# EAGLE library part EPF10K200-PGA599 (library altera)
EPF10K200 FLEX 10K family
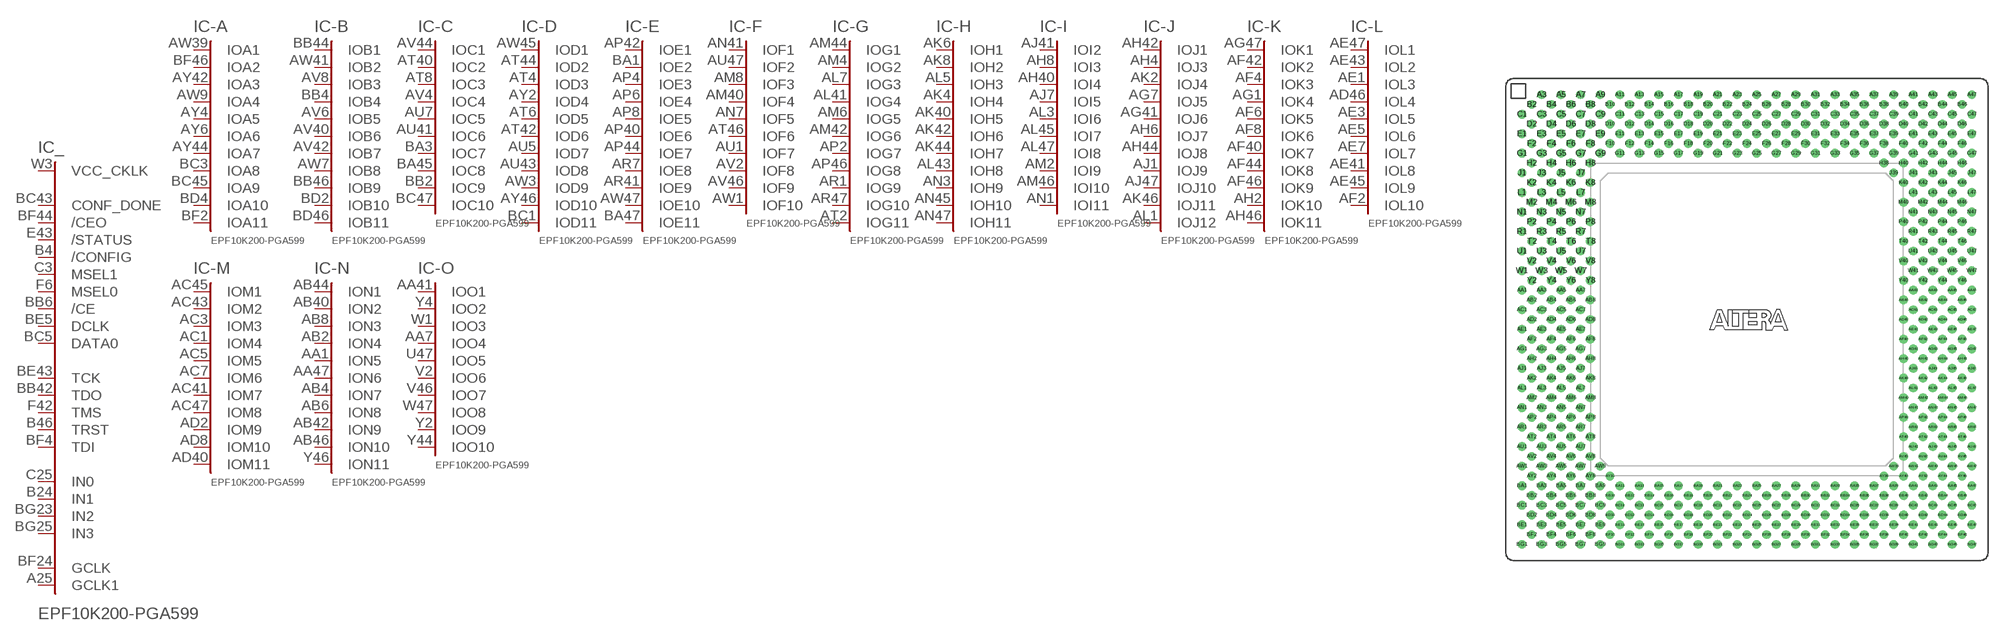
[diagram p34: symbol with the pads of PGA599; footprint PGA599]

Designator prefix IC; gates _=200P599C -A=A11-599 -B=B11-599 -C=C10-599 -D=D11-599 -E=E11-599 -F=F10-599 -G=G11-599 -H=H11-599 -I=I11-599 -J=J12-599 -K=K11-599 -L=L10-599 -M=M11-599 -N=N11-599 -O=O10-599 -P=P11-599 -Q=Q11-599 -R=R10-599 -S=S11-599 -T=T11-599 -U=U10-599 -V=V11-599 -W=W11-599 -X=X10-599 -1=IO44 -2=IO84 -3=IO124 -4=IO164 -5=IO204 -6=IO244 -7=IO284 -8=IO324 -9=IO364 -10=IO404 -11=IO444 -12=IO484 -13=IO524 G1=GND G2=GND G3=GND G4=GND G5=GND G6=GND G7=GND G8=GND G9=GND G10=GND G11=GND G12=GND G13=GND G14=GND G15=GND G16=GND G17=GND G18=GND G19=GND G20=GND G21=GND G22=GND G23=GND G24=GND G25=GND G26=GND G27=GND G28=GND G29=GND G30=GND G31=GND G32=GND G33=GND G34=GND G35=GND G36=GND G37=GND G38=GND G39=GND G40=GND G41=GND G42=GND G43=GND G44=GND G45=GND G46=GND G47=GND G48=GND G49=GND G50=GND G51=GND G52=GND G53=GND G54=GND G55=GND G56=GND G57=GND V1=VCCINT V2=VCCINT V3=VCCINT V4=VCCINT V5=VCCINT V6=VCCINT V7=VCCINT V8=VCCINT V9=VCCINT V10=VCCINT V11=VCCINT V12=VCCINT V13=VCCINT V14=VCCINT V15=VCCINT V16=VCCINT V17=VCCINT V18=VCCINT V19=VCCINT V20=VCCINT V21=VCCINT V22=VCCINT V23=VCCINT V24=VCCINT V25=VCCINT VO1=VCCIO VO2=VCCIO VO3=VCCIO VO4=VCCIO VO5=VCCIO VO6=VCCIO VO7=VCCIO VO8=VCCIO VO9=VCCIO VO10=VCCIO VO11=VCCIO VO12=VCCIO VO13=VCCIO VO14=VCCIO VO15=VCCIO VO16=VCCIO VO17=VCCIO VO18=VCCIO VO19=VCCIO VO20=VCCIO VO21=VCCIO VO22=VCCIO VO23=VCCIO VO24=VCCIO VO25=VCCIO VO26=VCCIO VO27=VCCIO VO28=VCCIO VO29=VCCIO VO30=VCCIO VO31=VCCIO VO32=VCCIO

## EPF10K200-PGA599 (OC_FARNELL: unknown; OC_NEWARK: unknown)  [PGA599]
A3  V5:VCC  pwr
A5  -2:IO52
A7  -2:IO82
A9  -3:IO101
A11  -3:IO111
A13  -4:IO131
A15  -4:IO161
A17  -5:IO191
A19  -6:IO214
A21  -6:IO234
A23  -7:IO263
A25  _:GCLK1  in
A27  -7:IO282
A29  -8:IO301
A31  -8:IO321
A33  -9:IO353
A35  -10:IO381
A37  -10:IO402
A39  -11:IO411
A41  -11:IO431
A43  -12:IO471
A45  V6:VCC  pwr
A47  G15:GND  pwr
AA1  -N:ION5
AA3  G1:GND  pwr
AA5  VO1:VCCIO  pwr
AA7  -O:IOO4
AA41  -O:IOO1
AA43  VO2:VCCIO  pwr
AA45  G2:GND  pwr
AA47  -N:ION6
AB2  -N:ION4
AB4  -N:ION7
AB6  -N:ION8
AB8  -N:ION3
AB40  -N:ION2
AB42  -N:ION9
AB44  -N:ION1
AB46  -N:ION10
AC1  -M:IOM4
AC3  -M:IOM3
AC5  -M:IOM5
AC7  -M:IOM6
AC41  -M:IOM7
AC43  -M:IOM2
AC45  -M:IOM1
AC47  -M:IOM8
AD2  -M:IOM9
AD4  VO3:VCCIO  pwr
AD6  G3:GND  pwr
AD8  -M:IOM10
AD40  -M:IOM11
AD42  G4:GND  pwr
AD44  VO4:VCCIO  pwr
AD46  -L:IOL4
AE1  -L:IOL3
AE3  -L:IOL5
AE5  -L:IOL6
AE7  -L:IOL7
AE41  -L:IOL8
AE43  -L:IOL2
AE45  -L:IOL9
AE47  -L:IOL1
AF2  -L:IOL10
AF4  -K:IOK3
AF6  -K:IOK5
AF8  -K:IOK6
AF40  -K:IOK7
AF42  -K:IOK2
AF44  -K:IOK8
AF46  -K:IOK9
AG1  -K:IOK4
AG3  G5:GND  pwr
AG5  VO5:VCCIO  pwr
AG7  -J:IOJ5
AG41  -J:IOJ6
AG43  VO6:VCCIO  pwr
AG45  G6:GND  pwr
AG47  -K:IOK1
AH2  -K:IOK10
AH4  -J:IOJ3
AH6  -J:IOJ7
AH8  -I:IOI3
AH40  -I:IOI4
AH42  -J:IOJ1
AH44  -J:IOJ8
AH46  -K:IOK11
AJ1  -J:IOJ9
AJ3  V1:VCC  pwr
AJ5  G7:GND  pwr
AJ7  -I:IOI5
AJ41  -I:IOI2
AJ43  G8:GND  pwr
AJ45  V2:VCC  pwr
AJ47  -J:IOJ10
AK2  -J:IOJ4
AK4  -H:IOH4
AK6  -H:IOH1
AK8  -H:IOH2
AK40  -H:IOH5
AK42  -H:IOH6
AK44  -H:IOH7
AK46  -J:IOJ11
AL1  -J:IOJ12
AL3  -I:IOI6
AL5  -H:IOH3
AL7  -G:IOG3
AL41  -G:IOG4
AL43  -H:IOH8
AL45  -I:IOI7
AL47  -I:IOI8
AM2  -I:IOI9
AM4  -G:IOG2
AM6  -G:IOG5
AM8  -F:IOF3
AM40  -F:IOF4
AM42  -G:IOG6
AM44  -G:IOG1
AM46  -I:IOI10
AN1  -I:IOI11
AN3  -H:IOH9
AN5  VO7:VCCIO  pwr
AN7  -F:IOF5
AN41  -F:IOF1
AN43  VO8:VCCIO  pwr
AN45  -H:IOH10
AN47  -H:IOH11
AP2  -G:IOG7
AP4  -E:IOE3
AP6  -E:IOE4
AP8  -E:IOE5
AP40  -E:IOE6
AP42  -E:IOE1
AP44  -E:IOE7
AP46  -G:IOG8
AR1  -G:IOG9
AR3  G9:GND  pwr
AR5  G10:GND  pwr
AR7  -E:IOE8
AR41  -E:IOE9
AR43  G11:GND  pwr
AR45  G12:GND  pwr
AR47  -G:IOG10
AT2  -G:IOG11
AT4  -D:IOD3
AT6  -D:IOD5
AT8  -C:IOC3
AT40  -C:IOC2
AT42  -D:IOD6
AT44  -D:IOD2
AT46  -F:IOF6
AU1  -F:IOF7
AU3  V3:VCC  pwr
AU5  -D:IOD7
AU7  -C:IOC5
AU41  -C:IOC6
AU43  -D:IOD8
AU45  V4:VCC  pwr
AU47  -F:IOF2
AV2  -F:IOF8
AV4  -C:IOC4
AV6  -B:IOB5
AV8  -B:IOB3
AV40  -B:IOB6
AV42  -B:IOB7
AV44  -C:IOC1
AV46  -F:IOF9
AW1  -F:IOF10
AW3  -D:IOD9
AW5  VO9:VCCIO  pwr
AW7  -B:IOB8
AW9  -A:IOA4
AW39  -A:IOA1
AW41  -B:IOB2
AW43  VO10:VCCIO  pwr
AW45  -D:IOD1
AW47  -E:IOE10
AY2  -D:IOD4
AY4  -A:IOA5
AY6  -A:IOA6
AY8  G13:GND  pwr
AY10  -1:IO12
AY38  -13:IO522
AY40  G14:GND  pwr
AY42  -A:IOA3
AY44  -A:IOA7
AY46  -D:IOD10
B2  G34:GND  pwr
B4  _:/CONFIG  in
B6  -1:IO21
B8  -2:IO74
B10  -3:IO91
B12  -3:IO121
B14  -4:IO141
B16  -5:IO171
B18  -5:IO201
B20  -6:IO224
B22  -6:IO244
B24  _:IN1  in
B26  -7:IO274
B28  -8:IO291
B30  -8:IO311
B32  -9:IO344
B34  -10:IO373
B36  -10:IO391
B38  -11:IO424
B40  -11:IO444
B42  -12:IO481
B44  -13:IO514
B46  _:TRST
BA1  -E:IOE2
BA3  -C:IOC7
BA5  G16:GND  pwr
BA7  VO11:VCCIO  pwr
BA9  -1:IO22
BA11  -1:IO42
BA13  -2:IO72
BA15  -3:IO103
BA17  -4:IO142
BA19  -5:IO183
BA21  -6:IO223
BA23  -7:IO252
BA25  -7:IO283
BA27  -8:IO313
BA29  -9:IO352
BA31  -10:IO392
BA33  -11:IO432
BA35  -12:IO463
BA37  -13:IO492
BA39  -13:IO512
BA41  VO12:VCCIO  pwr
BA43  G17:GND  pwr
BA45  -C:IOC8
BA47  -E:IOE11
BB2  -C:IOC9
BB4  -B:IOB4
BB6  _:/CE  in
BB8  -1:IO32
BB10  -2:IO53
BB12  -2:IO83
BB14  -3:IO113
BB16  -4:IO132
BB18  -5:IO173
BB20  -6:IO213
BB22  -6:IO243
BB24  G18:GND  pwr
BB26  -8:IO292
BB28  -8:IO323
BB30  -9:IO363
BB32  -10:IO403
BB34  -11:IO422
BB36  -12:IO452
BB38  -12:IO483
BB40  -13:IO502
BB42  _:TDO
BB44  -B:IOB1
BB46  -B:IOB9
BC1  -D:IOD11
BC3  -A:IOA8
BC5  _:DATA0  in
BC7  G19:GND  pwr
BC9  VO13:VCCIO  pwr
BC11  -2:IO62
BC13  G20:GND  pwr
BC15  VO14:VCCIO  pwr
BC17  -5:IO193
BC19  G21:GND  pwr
BC21  VO15:VCCIO  pwr
BC23  -7:IO261
BC25  -7:IO272
BC27  VO16:VCCIO  pwr
BC29  G22:GND  pwr
BC31  -9:IO342
BC33  VO17:VCCIO  pwr
BC35  G23:GND  pwr
BC37  -12:IO473
BC39  VO18:VCCIO  pwr
BC41  G24:GND  pwr
BC43  _:CONF_DONE  in
BC45  -A:IOA9
BC47  -C:IOC10
BD2  -B:IOB10
BD4  -A:IOA10
BD6  -1:IO13
BD8  -1:IO33
BD10  -3:IO93
BD12  -3:IO122
BD14  -4:IO152
BD16  -4:IO162
BD18  -5:IO203
BD20  -6:IO233
BD22  -7:IO251
BD24  VO19:VCCIO  pwr
BD26  -7:IO284
BD28  -8:IO303
BD30  -9:IO332
BD32  -10:IO372
BD34  -10:IO383
BD36  -11:IO412
BD38  -11:IO442
BD40  -13:IO501
BD42  -13:IO523
BD44  G25:GND  pwr
BD46  -B:IOB11
BE1  V7:VCC  pwr
BE3  G26:GND  pwr
BE5  _:DCLK  in
BE7  -1:IO43
BE9  -2:IO63
BE11  V8:VCC  pwr
BE13  G27:GND  pwr
BE15  -4:IO153
BE17  -5:IO182
BE19  V9:VCC  pwr
BE21  G28:GND  pwr
BE23  -7:IO262
BE25  -7:IO273
BE27  G29:GND  pwr
BE29  V10:VCC  pwr
BE31  -9:IO354
BE33  -10:IO382
BE35  G30:GND  pwr
BE37  V11:VCC  pwr
BE39  -12:IO472
BE41  -13:IO493
BE43  _:TCK
BE45  G31:GND  pwr
BE47  V12:VCC  pwr
BF2  -A:IOA11
BF4  _:TDI
BF6  -1:IO23
BF8  -2:IO73
BF10  -3:IO92
BF12  -3:IO123
BF14  -4:IO143
BF16  -5:IO172
BF18  -5:IO202
BF20  -6:IO222
BF22  -6:IO242
BF24  _:GCLK  in
BF26  -8:IO293
BF28  -8:IO312
BF30  -9:IO333
BF32  -9:IO364
BF34  -10:IO393
BF36  -11:IO413
BF38  -11:IO443
BF40  -12:IO462
BF42  -13:IO513
BF44  _:/CEO  in
BF46  -A:IOA2
BG1  G32:GND  pwr
BG3  V13:VCC  pwr
BG5  -2:IO54
BG7  -2:IO84
BG9  -3:IO102
BG11  -3:IO112
BG13  -4:IO133
BG15  -4:IO163
BG17  -5:IO192
BG19  -6:IO212
BG21  -6:IO232
BG23  _:IN2  in
BG25  _:IN3  in
BG27  -8:IO302
BG29  -8:IO322
BG31  -9:IO343
BG33  -10:IO371
BG35  -10:IO401
BG37  -11:IO423
BG39  -11:IO433
BG41  -12:IO453
BG43  -12:IO482
BG45  V14:VCC  pwr
BG47  G33:GND  pwr
C1  V15:VCC  pwr
C3  _:MSEL1  in
C5  -1:IO11
C7  -1:IO41
C9  -2:IO64
C11  V16:VCC  pwr
C13  G35:GND  pwr
C15  -4:IO151
C17  -5:IO181
C19  V17:VCC  pwr
C21  G36:GND  pwr
C23  -7:IO253
C25  _:IN0  in
C27  G37:GND  pwr
C29  V18:VCC  pwr
C31  -9:IO334
C33  -9:IO361
C35  G38:GND  pwr
C37  V19:VCC  pwr
C39  -12:IO461
C41  -13:IO503
C43  -13:IO524
C45  G39:GND  pwr
C47  V20:VCC  pwr
D2  -X:IOX5
D4  G40:GND  pwr
D6  -1:IO34
D8  -1:IO31
D10  -3:IO94
D12  -3:IO124
D14  -4:IO154
D16  -4:IO164
D18  -5:IO204
D20  -6:IO231
D22  -6:IO241
D24  VO20:VCCIO  pwr
D26  -8:IO294
D28  -8:IO304
D30  -9:IO331
D32  -10:IO374
D34  -10:IO384
D36  -11:IO414
D38  -11:IO441
D40  -12:IO474
D42  -13:IO491
D44  -X:IOX6
D46  -X:IOX7
E1  -X:IOX8
E3  -X:IOX4
E5  V21:VCC  pwr
E7  G41:GND  pwr
E9  VO21:VCCIO  pwr
E11  -2:IO61
E13  G42:GND  pwr
E15  VO22:VCCIO  pwr
E17  -5:IO194
E19  G43:GND  pwr
E21  VO23:VCCIO  pwr
E23  -7:IO264
E25  -7:IO271
E27  VO24:VCCIO  pwr
E29  G44:GND  pwr
E31  -9:IO341
E33  VO25:VCCIO  pwr
E35  G45:GND  pwr
E37  -12:IO454
E39  VO26:VCCIO  pwr
E41  G46:GND  pwr
E43  _:/STATUS  in
E45  -X:IOX1
E47  -W:IOW4
F2  -W:IOW5
F4  -W:IOW2
F6  _:MSEL0  in
F8  -1:IO24
F10  -2:IO51
F12  -2:IO81
F14  -3:IO114
F16  -4:IO134
F18  -5:IO174
F20  -6:IO211
F22  -7:IO254
F24  G47:GND  pwr
F26  -7:IO281
F28  -8:IO324
F30  -9:IO362
F32  -10:IO404
F34  -11:IO421
F36  -12:IO464
F38  -12:IO484
F40  -13:IO504
F42  _:TMS
F44  -W:IOW6
F46  -W:IOW1
G1  -U:IOU5
G3  -V:IOV5
G5  G48:GND  pwr
G7  VO27:VCCIO  pwr
G9  -1:IO14
G11  -1:IO44
G13  -2:IO71
G15  -3:IO104
G17  -4:IO144
G19  -5:IO184
G21  -6:IO221
G23  G49:GND  pwr
G25  V22:VCC  pwr
G27  -8:IO314
G29  -9:IO351
G31  -10:IO394
G33  -11:IO434
G35  -12:IO451
G37  -13:IO494
G39  -13:IO511
G41  VO28:VCCIO  pwr
G43  G50:GND  pwr
G45  -V:IOV2
G47  -U:IOU1
H2  -U:IOU3
H4  -V:IOV3
H6  -X:IOX9
H8  -X:IOX3
H38  -13:IO521
H40  G51:GND  pwr
H42  -X:IOX2
H44  -V:IOV6
H46  -U:IOU6
J1  -T:IOT4
J3  -U:IOU7
J5  VO29:VCCIO  pwr
J7  -W:IOW7
J39  -X:IOX10
J41  -W:IOW8
J43  VO30:VCCIO  pwr
J45  -T:IOT5
J47  -T:IOT6
K2  -S:IOS4
K4  -V:IOV7
K6  -W:IOW9
K8  -W:IOW3
K40  -U:IOU9
K42  -W:IOW11
K44  -V:IOV8
K46  -S:IOS1
L1  -S:IOS5
L3  V23:VCC  pwr
L5  -V:IOV9
L7  -V:IOV4
L41  -V:IOV1
L43  -V:IOV10
L45  V24:VCC  pwr
L47  -S:IOS6
M2  -S:IOS7
M4  -U:IOU4
M6  -U:IOU8
M8  -V:IOV11
M40  -W:IOW10
M42  -U:IOU2
M44  -U:IOU10
M46  -R:IOR3
N1  -R:IOR4
N3  G52:GND  pwr
N5  G53:GND  pwr
N7  -T:IOT7
N41  -T:IOT8
N43  G54:GND  pwr
N45  G55:GND  pwr
N47  -R:IOR1
P2  -R:IOR5
P4  -T:IOT9
P6  -T:IOT2
P8  -T:IOT3
P40  -T:IOT10
P42  -T:IOT1
P44  -T:IOT11
P46  -R:IOR6
R1  -Q:IOQ2
R3  -R:IOR7
R5  VO31:VCCIO  pwr
R7  -S:IOS8
R41  -S:IOS2
R43  VO32:VCCIO  pwr
R45  -Q:IOQ4
R47  -Q:IOQ5
T2  -P:IOP4
T4  -R:IOR8
T6  -S:IOS9
T8  -S:IOS3
T40  -S:IOS10
T42  -S:IOS11
T44  -R:IOR2
T46  -P:IOP5
U1  -P:IOP6
U3  -P:IOP2
U5  -Q:IOQ6
U7  -R:IOR9
U41  -R:IOR10
U43  -Q:IOQ7
U45  -P:IOP1
U47  -O:IOO5
V2  -O:IOO6
V4  -Q:IOQ8
V6  -Q:IOQ3
V8  -Q:IOQ9
V40  -Q:IOQ10
V42  -Q:IOQ1
V44  -Q:IOQ11
V46  -O:IOO7
W1  -O:IOO3
W3  _:VCC_CKLK  pas
W5  G56:GND  pwr
W7  -P:IOP7
W41  -P:IOP8
W43  G57:GND  pwr
W45  V25:VCC  pwr
W47  -O:IOO8
Y2  -O:IOO9
Y4  -O:IOO2
Y6  -P:IOP3
Y8  -P:IOP9
Y40  -P:IOP10
Y42  -P:IOP11
Y44  -O:IOO10
Y46  -N:ION11

## Footprint PGA599 (pad centres in mm)
Pin Grid Array
drill 0.61 pad 1.016 round: A3 -26.67,29.21; A5 -24.13,29.21; A7 -21.59,29.21; A9 -19.05,29.21; A11 -16.51,29.21; A13 -13.97,29.21; A15 -11.43,29.21; A17 -8.89,29.21; A19 -6.35,29.21; A21 -3.81,29.21; A23 -1.27,29.21; A25 1.27,29.21; A27 3.81,29.21; A29 6.35,29.21; A31 8.89,29.21; A33 11.43,29.21; A35 13.97,29.21; A37 16.51,29.21; A39 19.05,29.21; A41 21.59,29.21; A43 24.13,29.21; A45 26.67,29.21; A47 29.21,29.21; AA1 -29.21,3.81; AA3 -26.67,3.81; AA5 -24.13,3.81; AA7 -21.59,3.81; AA41 21.59,3.81; AA43 24.13,3.81; AA45 26.67,3.81; AA47 29.21,3.81; AB2 -27.94,2.54; AB4 -25.4,2.54; AB6 -22.86,2.54; AB8 -20.32,2.54; AB40 20.32,2.54; AB42 22.86,2.54; AB44 25.4,2.54; AB46 27.94,2.54; AC1 -29.21,1.27; AC3 -26.67,1.27; AC5 -24.13,1.27; AC7 -21.59,1.27; AC41 21.59,1.27; AC43 24.13,1.27; AC45 26.67,1.27; AC47 29.21,1.27; AD2 -27.94,0; AD4 -25.4,0; AD6 -22.86,0; AD8 -20.32,0; AD40 20.32,0; AD42 22.86,0; AD44 25.4,0; AD46 27.94,0; AE1 -29.21,-1.27; AE3 -26.67,-1.27; AE5 -24.13,-1.27; AE7 -21.59,-1.27; AE41 21.59,-1.27; AE43 24.13,-1.27; AE45 26.67,-1.27; AE47 29.21,-1.27; AF2 -27.94,-2.54; AF4 -25.4,-2.54; AF6 -22.86,-2.54; AF8 -20.32,-2.54; AF40 20.32,-2.54; AF42 22.86,-2.54; AF44 25.4,-2.54; AF46 27.94,-2.54; AG1 -29.21,-3.81; AG3 -26.67,-3.81; AG5 -24.13,-3.81; AG7 -21.59,-3.81; AG41 21.59,-3.81; AG43 24.13,-3.81; AG45 26.67,-3.81; AG47 29.21,-3.81; AH2 -27.94,-5.08; AH4 -25.4,-5.08; AH6 -22.86,-5.08; AH8 -20.32,-5.08; AH40 20.32,-5.08; AH42 22.86,-5.08; AH44 25.4,-5.08; AH46 27.94,-5.08; AJ1 -29.21,-6.35; AJ3 -26.67,-6.35; AJ5 -24.13,-6.35; AJ7 -21.59,-6.35; AJ41 21.59,-6.35; AJ43 24.13,-6.35; AJ45 26.67,-6.35; AJ47 29.21,-6.35; AK2 -27.94,-7.62; AK4 -25.4,-7.62; AK6 -22.86,-7.62; AK8 -20.32,-7.62; AK40 20.32,-7.62; AK42 22.86,-7.62; AK44 25.4,-7.62; AK46 27.94,-7.62; AL1 -29.21,-8.89; AL3 -26.67,-8.89; AL5 -24.13,-8.89; AL7 -21.59,-8.89; AL41 21.59,-8.89; AL43 24.13,-8.89; AL45 26.67,-8.89; AL47 29.21,-8.89; AM2 -27.94,-10.16; AM4 -25.4,-10.16; AM6 -22.86,-10.16; AM8 -20.32,-10.16; AM40 20.32,-10.16; AM42 22.86,-10.16; AM44 25.4,-10.16; AM46 27.94,-10.16; AN1 -29.21,-11.43; AN3 -26.67,-11.43; AN5 -24.13,-11.43; AN7 -21.59,-11.43; AN41 21.59,-11.43; AN43 24.13,-11.43; AN45 26.67,-11.43; AN47 29.21,-11.43; AP2 -27.94,-12.7; AP4 -25.4,-12.7; AP6 -22.86,-12.7; AP8 -20.32,-12.7; AP40 20.32,-12.7; AP42 22.86,-12.7; AP44 25.4,-12.7; AP46 27.94,-12.7; AR1 -29.21,-13.97; AR3 -26.67,-13.97; AR5 -24.13,-13.97; AR7 -21.59,-13.97; AR41 21.59,-13.97; AR43 24.13,-13.97; AR45 26.67,-13.97; AR47 29.21,-13.97; AT2 -27.94,-15.24; AT4 -25.4,-15.24; AT6 -22.86,-15.24; AT8 -20.32,-15.24; AT40 20.32,-15.24; AT42 22.86,-15.24; AT44 25.4,-15.24; AT46 27.94,-15.24; AU1 -29.21,-16.51; AU3 -26.67,-16.51; AU5 -24.13,-16.51; AU7 -21.59,-16.51; AU41 21.59,-16.51; AU43 24.13,-16.51; AU45 26.67,-16.51; AU47 29.21,-16.51; AV2 -27.94,-17.78; AV4 -25.4,-17.78; AV6 -22.86,-17.78; AV8 -20.32,-17.78; AV40 20.32,-17.78; AV42 22.86,-17.78; AV44 25.4,-17.78; AV46 27.94,-17.78; AW1 -29.21,-19.05; AW3 -26.67,-19.05; AW5 -24.13,-19.05; AW7 -21.59,-19.05; AW9 -19.05,-19.05; AW39 19.05,-19.05; AW41 21.59,-19.05; AW43 24.13,-19.05; AW45 26.67,-19.05; AW47 29.21,-19.05; AY2 -27.94,-20.32; AY4 -25.4,-20.32; AY6 -22.86,-20.32; AY8 -20.32,-20.32; AY10 -17.78,-20.32; AY38 17.78,-20.32; AY40 20.32,-20.32; AY42 22.86,-20.32; AY44 25.4,-20.32; AY46 27.94,-20.32; B2 -27.94,27.94; B4 -25.4,27.94; B6 -22.86,27.94; B8 -20.32,27.94; B10 -17.78,27.94; B12 -15.24,27.94; B14 -12.7,27.94; B16 -10.16,27.94; B18 -7.62,27.94; B20 -5.08,27.94; B22 -2.54,27.94; B24 0,27.94; B26 2.54,27.94; B28 5.08,27.94; B30 7.62,27.94; B32 10.16,27.94; B34 12.7,27.94; B36 15.24,27.94; B38 17.78,27.94; B40 20.32,27.94; B42 22.86,27.94; B44 25.4,27.94; B46 27.94,27.94; BA1 -29.21,-21.59; BA3 -26.67,-21.59; BA5 -24.13,-21.59; BA7 -21.59,-21.59; BA9 -19.05,-21.59; BA11 -16.51,-21.59; BA13 -13.97,-21.59; BA15 -11.43,-21.59; BA17 -8.89,-21.59; BA19 -6.35,-21.59; BA21 -3.81,-21.59; BA23 -1.27,-21.59; BA25 1.27,-21.59; BA27 3.81,-21.59; BA29 6.35,-21.59; BA31 8.89,-21.59; BA33 11.43,-21.59; BA35 13.97,-21.59; BA37 16.51,-21.59; BA39 19.05,-21.59; BA41 21.59,-21.59; BA43 24.13,-21.59; BA45 26.67,-21.59; BA47 29.21,-21.59; BB2 -27.94,-22.86; BB4 -25.4,-22.86; BB6 -22.86,-22.86; BB8 -20.32,-22.86; BB10 -17.78,-22.86; BB12 -15.24,-22.86; BB14 -12.7,-22.86; BB16 -10.16,-22.86; BB18 -7.62,-22.86; BB20 -5.08,-22.86; BB22 -2.54,-22.86; BB24 0,-22.86; BB26 2.54,-22.86; BB28 5.08,-22.86; BB30 7.62,-22.86; BB32 10.16,-22.86; BB34 12.7,-22.86; BB36 15.24,-22.86; BB38 17.78,-22.86; BB40 20.32,-22.86; BB42 22.86,-22.86; BB44 25.4,-22.86; BB46 27.94,-22.86; BC1 -29.21,-24.13; BC3 -26.67,-24.13; BC5 -24.13,-24.13; BC7 -21.59,-24.13; BC9 -19.05,-24.13; BC11 -16.51,-24.13; BC13 -13.97,-24.13; BC15 -11.43,-24.13; BC17 -8.89,-24.13; BC19 -6.35,-24.13; BC21 -3.81,-24.13; BC23 -1.27,-24.13; BC25 1.27,-24.13; BC27 3.81,-24.13; BC29 6.35,-24.13; BC31 8.89,-24.13; BC33 11.43,-24.13; BC35 13.97,-24.13; BC37 16.51,-24.13; BC39 19.05,-24.13; BC41 21.59,-24.13; BC43 24.13,-24.13; BC45 26.67,-24.13; BC47 29.21,-24.13; BD2 -27.94,-25.4; BD4 -25.4,-25.4; BD6 -22.86,-25.4; BD8 -20.32,-25.4; BD10 -17.78,-25.4; BD12 -15.24,-25.4; BD14 -12.7,-25.4; BD16 -10.16,-25.4; BD18 -7.62,-25.4; BD20 -5.08,-25.4; BD22 -2.54,-25.4; BD24 0,-25.4; BD26 2.54,-25.4; BD28 5.08,-25.4; BD30 7.62,-25.4; BD32 10.16,-25.4; BD34 12.7,-25.4; BD36 15.24,-25.4; BD38 17.78,-25.4; BD40 20.32,-25.4; BD42 22.86,-25.4; BD44 25.4,-25.4; BD46 27.94,-25.4; BE1 -29.21,-26.67; BE3 -26.67,-26.67; BE5 -24.13,-26.67; BE7 -21.59,-26.67; BE9 -19.05,-26.67; BE11 -16.51,-26.67; BE13 -13.97,-26.67; BE15 -11.43,-26.67; BE17 -8.89,-26.67; BE19 -6.35,-26.67; BE21 -3.81,-26.67; BE23 -1.27,-26.67; BE25 1.27,-26.67; BE27 3.81,-26.67; BE29 6.35,-26.67; BE31 8.89,-26.67; BE33 11.43,-26.67; BE35 13.97,-26.67; BE37 16.51,-26.67; BE39 19.05,-26.67; BE41 21.59,-26.67; BE43 24.13,-26.67; BE45 26.67,-26.67; BE47 29.21,-26.67; BF2 -27.94,-27.94; BF4 -25.4,-27.94; BF6 -22.86,-27.94; BF8 -20.32,-27.94; BF10 -17.78,-27.94; BF12 -15.24,-27.94; BF14 -12.7,-27.94; BF16 -10.16,-27.94; BF18 -7.62,-27.94; BF20 -5.08,-27.94; BF22 -2.54,-27.94; BF24 0,-27.94; BF26 2.54,-27.94; BF28 5.08,-27.94; BF30 7.62,-27.94; BF32 10.16,-27.94; BF34 12.7,-27.94; BF36 15.24,-27.94; BF38 17.78,-27.94; BF40 20.32,-27.94; BF42 22.86,-27.94; BF44 25.4,-27.94; BF46 27.94,-27.94; BG1 -29.21,-29.21; BG3 -26.67,-29.21; BG5 -24.13,-29.21; BG7 -21.59,-29.21; BG9 -19.05,-29.21; BG11 -16.51,-29.21; BG13 -13.97,-29.21; BG15 -11.43,-29.21; BG17 -8.89,-29.21; BG19 -6.35,-29.21; BG21 -3.81,-29.21; BG23 -1.27,-29.21; BG25 1.27,-29.21; BG27 3.81,-29.21; BG29 6.35,-29.21; BG31 8.89,-29.21; BG33 11.43,-29.21; BG35 13.97,-29.21; BG37 16.51,-29.21; BG39 19.05,-29.21; BG41 21.59,-29.21; BG43 24.13,-29.21; BG45 26.67,-29.21; BG47 29.21,-29.21; C1 -29.21,26.67; C3 -26.67,26.67; C5 -24.13,26.67; C7 -21.59,26.67; C9 -19.05,26.67; C11 -16.51,26.67; C13 -13.97,26.67; C15 -11.43,26.67; C17 -8.89,26.67; C19 -6.35,26.67; C21 -3.81,26.67; C23 -1.27,26.67; C25 1.27,26.67; C27 3.81,26.67; C29 6.35,26.67; C31 8.89,26.67; C33 11.43,26.67; C35 13.97,26.67; C37 16.51,26.67; C39 19.05,26.67; C41 21.59,26.67; C43 24.13,26.67; C45 26.67,26.67; C47 29.21,26.67; D2 -27.94,25.4; D4 -25.4,25.4; D6 -22.86,25.4; D8 -20.32,25.4; D10 -17.78,25.4; D12 -15.24,25.4; D14 -12.7,25.4; D16 -10.16,25.4; D18 -7.62,25.4; D20 -5.08,25.4; D22 -2.54,25.4; D24 0,25.4; D26 2.54,25.4; D28 5.08,25.4; D30 7.62,25.4; D32 10.16,25.4; D34 12.7,25.4; D36 15.24,25.4; D38 17.78,25.4; D40 20.32,25.4; D42 22.86,25.4; D44 25.4,25.4; D46 27.94,25.4; E1 -29.21,24.13; E3 -26.67,24.13; E5 -24.13,24.13; E7 -21.59,24.13; E9 -19.05,24.13; E11 -16.51,24.13; E13 -13.97,24.13; E15 -11.43,24.13; E17 -8.89,24.13; E19 -6.35,24.13; E21 -3.81,24.13; E23 -1.27,24.13; E25 1.27,24.13; E27 3.81,24.13; E29 6.35,24.13; E31 8.89,24.13; E33 11.43,24.13; E35 13.97,24.13; E37 16.51,24.13; E39 19.05,24.13; E41 21.59,24.13; E43 24.13,24.13; E45 26.67,24.13; E47 29.21,24.13; F2 -27.94,22.86; F4 -25.4,22.86; F6 -22.86,22.86; F8 -20.32,22.86; F10 -17.78,22.86; F12 -15.24,22.86; F14 -12.7,22.86; F16 -10.16,22.86; F18 -7.62,22.86; F20 -5.08,22.86; F22 -2.54,22.86; F24 0,22.86; F26 2.54,22.86; F28 5.08,22.86; F30 7.62,22.86; F32 10.16,22.86; F34 12.7,22.86; F36 15.24,22.86; F38 17.78,22.86; F40 20.32,22.86; F42 22.86,22.86; F44 25.4,22.86; F46 27.94,22.86; G1 -29.21,21.59; G3 -26.67,21.59; G5 -24.13,21.59; G7 -21.59,21.59; G9 -19.05,21.59; G11 -16.51,21.59; G13 -13.97,21.59; G15 -11.43,21.59; G17 -8.89,21.59; G19 -6.35,21.59; G21 -3.81,21.59; G23 -1.27,21.59; G25 1.27,21.59; G27 3.81,21.59; G29 6.35,21.59; G31 8.89,21.59; G33 11.43,21.59; G35 13.97,21.59; G37 16.51,21.59; G39 19.05,21.59; G41 21.59,21.59; G43 24.13,21.59; G45 26.67,21.59; G47 29.21,21.59; H2 -27.94,20.32; H4 -25.4,20.32; H6 -22.86,20.32; H8 -20.32,20.32; H38 17.78,20.32; H40 20.32,20.32; H42 22.86,20.32; H44 25.4,20.32; H46 27.94,20.32; J1 -29.21,19.05; J3 -26.67,19.05; J5 -24.13,19.05; J7 -21.59,19.05; J39 19.05,19.05; J41 21.59,19.05; J43 24.13,19.05; J45 26.67,19.05; J47 29.21,19.05; K2 -27.94,17.78; K4 -25.4,17.78; K6 -22.86,17.78; K8 -20.32,17.78; K40 20.32,17.78; K42 22.86,17.78; K44 25.4,17.78; K46 27.94,17.78; L1 -29.21,16.51; L3 -26.67,16.51; L5 -24.13,16.51; L7 -21.59,16.51; L41 21.59,16.51; L43 24.13,16.51; L45 26.67,16.51; L47 29.21,16.51; M2 -27.94,15.24; M4 -25.4,15.24; M6 -22.86,15.24; M8 -20.32,15.24; M40 20.32,15.24; M42 22.86,15.24; M44 25.4,15.24; M46 27.94,15.24; N1 -29.21,13.97; N3 -26.67,13.97; N5 -24.13,13.97; N7 -21.59,13.97; N41 21.59,13.97; N43 24.13,13.97; N45 26.67,13.97; N47 29.21,13.97; P2 -27.94,12.7; P4 -25.4,12.7; P6 -22.86,12.7; P8 -20.32,12.7; P40 20.32,12.7; P42 22.86,12.7; P44 25.4,12.7; P46 27.94,12.7; R1 -29.21,11.43; R3 -26.67,11.43; R5 -24.13,11.43; R7 -21.59,11.43; R41 21.59,11.43; R43 24.13,11.43; R45 26.67,11.43; R47 29.21,11.43; T2 -27.94,10.16; T4 -25.4,10.16; T6 -22.86,10.16; T8 -20.32,10.16; T40 20.32,10.16; T42 22.86,10.16; T44 25.4,10.16; T46 27.94,10.16; U1 -29.21,8.89; U3 -26.67,8.89; U5 -24.13,8.89; U7 -21.59,8.89; U41 21.59,8.89; U43 24.13,8.89; U45 26.67,8.89; U47 29.21,8.89; V2 -27.94,7.62; V4 -25.4,7.62; V6 -22.86,7.62; V8 -20.32,7.62; V40 20.32,7.62; V42 22.86,7.62; V44 25.4,7.62; V46 27.94,7.62; W1 -29.21,6.35; W3 -26.67,6.35; W5 -24.13,6.35; W7 -21.59,6.35; W41 21.59,6.35; W43 24.13,6.35; W45 26.67,6.35; W47 29.21,6.35; Y2 -27.94,5.08; Y4 -25.4,5.08; Y6 -22.86,5.08; Y8 -20.32,5.08; Y40 20.32,5.08; Y42 22.86,5.08; Y44 25.4,5.08; Y46 27.94,5.08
